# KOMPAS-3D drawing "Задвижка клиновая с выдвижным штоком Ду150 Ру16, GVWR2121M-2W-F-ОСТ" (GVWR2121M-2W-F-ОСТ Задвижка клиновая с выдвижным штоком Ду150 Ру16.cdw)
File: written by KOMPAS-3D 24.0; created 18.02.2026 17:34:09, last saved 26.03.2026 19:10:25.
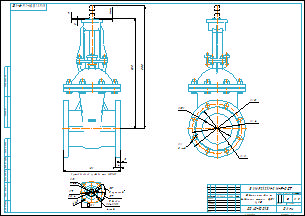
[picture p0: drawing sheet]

Document properties: art: D040-10013; Автор: R2D2; Форматы листов документа: A2; Полное имя файла: GVWR2121M-2W-F-ОСТ Задвижка клиновая с видвижным штоком Ду150 Ру16.cdw; Масса: 60; Наименование: Задвижка клиновая с выдвижным штоком Ду150 Ру16; Количество листов документа: 1; Примечание: D040-10013

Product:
- Part/product: Задвижка клиновая с выдвижным штоком Ду150 Ру16  | designation GVWR2121M-2W-F-ОСТ
    Масса: 60
    Раздел спецификации: Прочие изделия
    Форматы листов документа: A2
    Примечание: D040-10013
    additional columns: D040-10013

Views: Проекционный вид 3
Referenced files in E:\Работа\Зайцев\Для компаса\: чертеж DN.ru А3.cdt
Referenced files in E:\Работа\Зайцев\GVWR2121M-2W-F-ОСТ Задвижка клиновая с видвижным штоком Ду50-300 Ру16\DN150\: GVWR2121M-2W-F-ОСТ Задвижка клиновая с выдвижным штоком Ду150 Ру16.m3d
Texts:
  Присоединение привода тип АК (А)
  чертеж DN.ru А3.cdt
  Задвижка клиновая с
  выдвижным штоком Ду150
  Ру16
  GVWR2121M-2W-F-ОСТ
  Задвижка клиновая с выдвижным штоком Ду150 Ру16
  GVWR2121M-2W-F-ОСТ Задвижка клиновая с выдвижным штоком Ду150 Ру16
Dimensions and other numbers on the sheet: 100; 5 кулачков; 5 впадин; 14 (М12); 4 отв.; 13,5; 104; 70; 44; 32; 1:2,5; 0; 1; 2; 60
